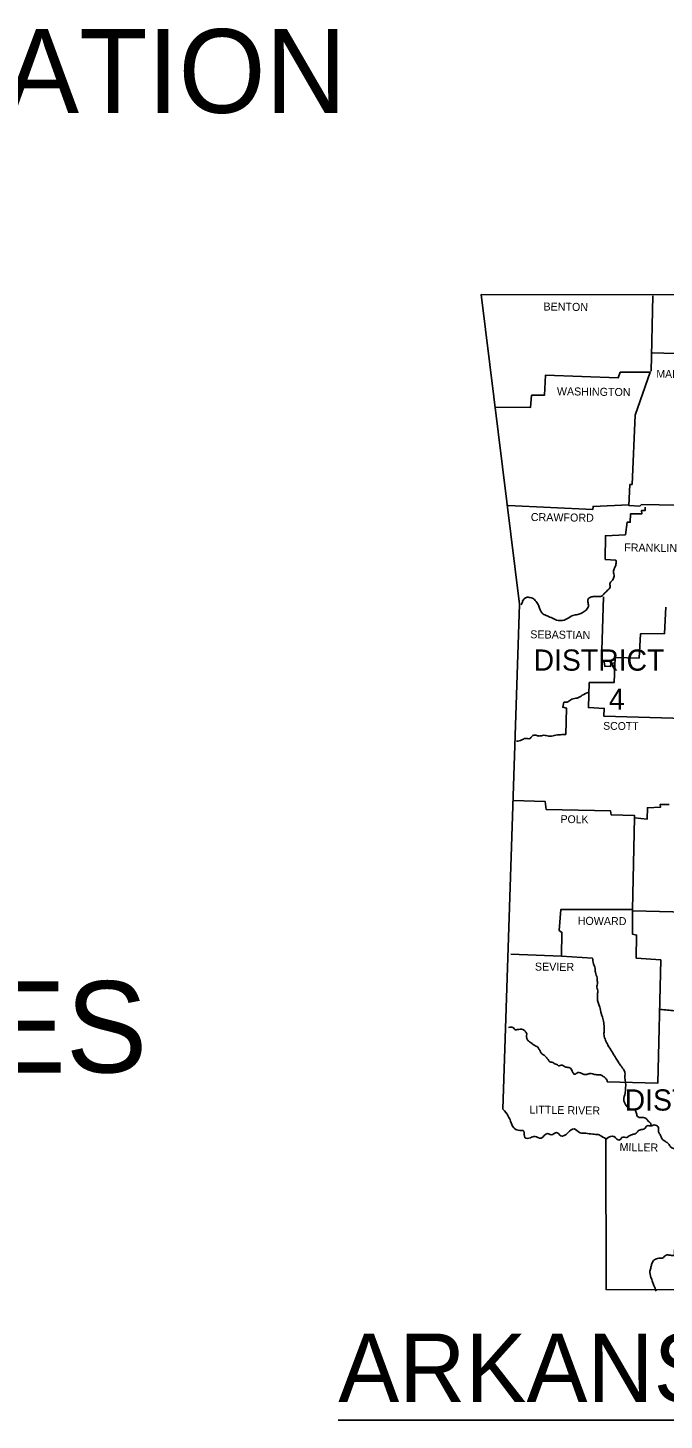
# Model space of a CAD drawing. Extents: x -2512 to 3792, y -435 to 2624.
# Drawn here: x 2465 to 2800, y 1365 to 2097 of the extents above; entities that cross this region are included whole.
import ezdxf

# ---------------------------------------------------------------- set-up
doc = ezdxf.new("R2010")
doc.units = 0
for name, color, linetype in [('1', 7, 'Continuous'), ('2', 7, 'Continuous'), ('3', 7, 'Continuous')]:
    doc.layers.add(name, color=color, linetype=linetype)

msp = doc.modelspace()

# ---------------------------------------------------------------- linework, layer by layer
at = {"layer": '1'}
for points in [[(2703.71, 1956.42), (2861.92, 1956.32), (3000.75, 1956.61), (3164.54, 1959.16), (3240.46, 1960.92)], [(2703.71, 1956.42), (2723.96, 1793.81), (2715.15, 1528.37)], [(2794.01, 1955.83), (2793.13, 1916.21)], [(2793.82, 1925.89), (2817.89, 1925.11), (2818.47, 1921.98), (2821.8, 1921.88), (2821.7, 1919.92), (2824.05, 1919.34), (2824.25, 1908.67), (2827.28, 1907.99), (2827.48, 1903.78), (2831.78, 1903.19), (2831.98, 1899.28), (2840.49, 1898.4), (2862.4, 1898.89), (2862.6, 1955.15)], [(2711.44, 1897.22), (2729.73, 1897.13), (2730.22, 1903.58), (2736.97, 1903.58), (2737.56, 1914.05), (2775.72, 1912.68), (2776.89, 1915.62), (2792.64, 1915.72), (2784.72, 1893.02), (2783.15, 1856.72), (2781.98, 1856.62), (2781.39, 1845.66), (2787.17, 1845.17), (2788.05, 1846.05), (2834.72, 1845.17), (2835.21, 1839.99)], [(2717.89, 1845.56), (2762.41, 1843.51), (2762.61, 1845.08), (2781.2, 1845.96)], [(2790, 1844.78), (2790, 1843.02), (2788.14, 1843.02), (2788.24, 1841.26), (2782.27, 1841.16), (2782.18, 1836.76), (2780.51, 1836.76), (2779.63, 1830.2), (2769.06, 1829.71), (2768.97, 1817.29), (2774.64, 1816.9)], [(2767.99, 1797.53), (2767.01, 1763.87), (2768.48, 1763.48), (2768.77, 1761.13), (2771.71, 1760.93), (2772, 1762.6), (2774.35, 1762.99)], [(2800.86, 1792.24), (2800.18, 1778.25), (2787.46, 1778.15), (2786.77, 1765.43), (2774.15, 1765.73), (2773.76, 1752.62), (2760.55, 1752.52), (2760.16, 1739.41), (2768.48, 1738.92), (2768.18, 1734.91), (2810.65, 1733.73)], [(2748.32, 1725.22), (2748.62, 1739.02), (2746.66, 1739.6), (2747.25, 1742.25)], [(2720.54, 1690.59), (2737.46, 1690), (2737.85, 1685.89), (2771.71, 1685.2), (2772.1, 1683.05), (2784.43, 1682.66), (2784.33, 1680.8)], [(2802.53, 1688.53), (2797.93, 1688.53), (2798.03, 1686.97), (2791.18, 1686.77), (2791.08, 1680.8), (2784.43, 1681.39), (2783.35, 1633.25), (2745.68, 1633.35), (2744.8, 1622.19), (2746.17, 1621.22), (2746.07, 1608.69), (2719.36, 1609.87)], [(2783.35, 1633.25), (2783.35, 1620.24), (2785.5, 1619.85), (2785.31, 1607.71), (2798.22, 1606.74), (2796.66, 1542.06), (2770.04, 1542.75)], [(2783.55, 1632.57), (2839.51, 1631.1)], [(2746.07, 1608.69), (2762.31, 1607.71)], [(2769.26, 1512.61), (2769.46, 1433.46), (3128.04, 1432.87)]]:
    msp.add_lwpolyline(points, dxfattribs=at)
for points in [[(2774.64, 1816.9), (2774.64, 1814.84), (2773.86, 1812.69), (2773.37, 1810.83), (2773.66, 1808.39), (2772.78, 1806.43), (2771.51, 1804.86), (2771.51, 1802.91), (2770.04, 1800.85), (2768.48, 1799.29), (2767.11, 1798.01), (2764.66, 1797.82), (2762.61, 1797.72), (2760.55, 1797.04), (2759.77, 1795.57), (2760.16, 1793.32), (2759.38, 1791.17), (2757.32, 1789.5), (2755.07, 1788.43), (2752.73, 1788.03), (2749.5, 1786.47), (2746.56, 1785.2), (2743.43, 1785.39), (2740.5, 1786.66), (2737.85, 1787.84), (2735.8, 1789.01), (2734.14, 1792.63), (2733.06, 1794.59), (2731.2, 1796.55), (2728.95, 1797.33), (2727.09, 1797.13), (2724.84, 1793.32)], [(2747.25, 1742.25), (2749.4, 1742.44), (2751.45, 1743.81), (2754.19, 1744.4), (2756.93, 1745.87), (2760.36, 1747.43)], [(2748.32, 1725.22), (2745.49, 1725.12), (2742.26, 1724.73), (2739.32, 1724.34), (2736.68, 1724.83), (2734.23, 1724.44), (2732.57, 1724.83), (2730.52, 1724.34), (2729.34, 1723.17), (2726.9, 1723.17), (2725.13, 1722.38), (2722.3, 1721.7)], [(2762.31, 1607.71), (2762.8, 1604.78), (2763.68, 1602.24), (2763.78, 1600.28), (2764.66, 1597.34), (2764.66, 1596.27), (2764.96, 1594.11), (2764.56, 1592.94), (2765.05, 1590.59), (2764.96, 1588.83), (2764.96, 1587.36), (2765.05, 1584.92), (2765.84, 1582.76), (2766.62, 1579.54), (2767.11, 1577.87), (2767.89, 1575.33), (2768.38, 1572.2), (2768.48, 1569.85), (2768.28, 1567.7), (2768.87, 1565.25), (2769.95, 1562.81), (2771.32, 1560.46), (2772.98, 1557.82), (2774.15, 1555.76), (2775.62, 1553.51), (2776.79, 1551.65), (2778.56, 1549.3), (2779.34, 1547.35), (2779.34, 1544.61), (2779.73, 1542.06), (2779.63, 1539.23), (2779.44, 1536.68), (2778.75, 1533.16), (2779.24, 1531.5), (2781.1, 1529.05), (2782.27, 1528.37), (2784.33, 1527.97), (2785.31, 1526.6), (2785.89, 1524.55), (2787.95, 1523.86), (2790.2, 1523.67), (2791.27, 1522.49), (2792.74, 1520.93), (2793.23, 1520.15)], [(2798.03, 1580.71), (2801.74, 1580.42), (2805.17, 1580.03), (2807.81, 1579.73), (2810.55, 1578.75), (2813, 1577.87), (2814.56, 1577.19), (2817.2, 1577.38), (2819.45, 1576.89), (2822, 1576.01), (2823.86, 1574.35), (2825.03, 1573.08), (2827.28, 1572.59), (2829.14, 1572.88), (2831.39, 1572.69), (2833.93, 1571.9), (2835.99, 1572), (2837.65, 1572.39), (2839.61, 1572.88), (2842.05, 1573.08), (2843.91, 1572.69), (2846.36, 1572.59), (2849.2, 1572.88), (2852.72, 1571.9)], [(2718.19, 1571.22), (2720.34, 1571.32), (2721.81, 1570.05), (2722.69, 1570.14), (2724.25, 1570.34), (2725.72, 1570.24), (2726.8, 1569.36), (2727.68, 1567.8), (2727.58, 1566.33), (2727.68, 1565.74), (2728.36, 1564.47), (2729.54, 1563.49), (2730.81, 1562.51), (2731.98, 1561.73), (2733.94, 1560.46), (2734.14, 1560.07), (2734.92, 1558.5), (2735.9, 1557.23), (2737.07, 1556.45), (2738.34, 1555.08), (2738.93, 1554.49), (2739.91, 1553.12), (2740.98, 1553.02), (2742.45, 1552.14), (2743.53, 1551.85), (2744.7, 1551.06), (2745.88, 1551.46), (2747.34, 1550.87), (2749.3, 1550.28), (2750.38, 1550.09), (2751.65, 1548.23), (2752.92, 1546.66), (2754.49, 1547.54), (2757.42, 1546.66), (2759.28, 1546.56), (2760.94, 1547.05), (2762.22, 1546.96), (2764.56, 1546.37), (2766.03, 1546.37), (2767.6, 1545.78), (2769.06, 1544.61), (2770.04, 1543.34), (2770.04, 1542.75)], [(2715.15, 1528.37), (2717.99, 1524.65), (2719.17, 1522.01), (2720.83, 1518.58), (2723.28, 1517.21), (2726.11, 1516.72), (2726.7, 1513.4), (2729.63, 1513.3), (2731.98, 1513.98), (2735.21, 1513.1), (2738.64, 1515.45), (2740.59, 1514.86), (2743.43, 1516.04), (2745.58, 1514.28), (2749.3, 1515.84), (2752.63, 1517.99), (2755.76, 1515.94), (2758.79, 1515.65), (2762.41, 1515.16), (2765.25, 1514.96), (2767.79, 1513.69), (2769.65, 1512.42), (2769.26, 1512.61)], [(2769.26, 1512.61), (2772.68, 1514.08), (2774.15, 1513.59), (2775.42, 1512.32), (2776.89, 1512.32), (2777.67, 1513.49), (2779.14, 1513.59), (2780.32, 1513.49), (2781.59, 1514.28), (2782.66, 1514.77), (2784.13, 1515.25), (2785.21, 1515.65), (2786.19, 1516.72), (2787.95, 1517.6), (2790, 1518.29), (2790.59, 1519.27), (2791.57, 1519.66), (2793.52, 1519.56), (2794.8, 1520.15), (2795.87, 1519.66), (2796.85, 1518.97), (2797.05, 1516.43), (2797.83, 1515.06), (2799, 1512.61), (2800.67, 1511.34), (2802.23, 1510.07), (2802.82, 1509.29), (2804.48, 1507.82), (2805.95, 1507.33), (2806.64, 1506.25), (2807.71, 1503.71), (2809.28, 1501.46)], [(2809.28, 1501.46), (2808.69, 1498.62), (2808.59, 1496.37), (2809.08, 1493.73), (2808.59, 1492.46), (2809.38, 1490.6), (2810.84, 1489.13), (2811.92, 1487.57), (2812.6, 1485.32), (2811.72, 1482.77), (2812.7, 1480.13), (2813.58, 1479.15), (2814.07, 1477.59), (2813.39, 1474.55), (2812.51, 1472.3), (2810.55, 1470.05), (2809.96, 1468.98), (2810.26, 1467.51), (2810.74, 1465.16), (2810.26, 1464.48), (2808.98, 1462.81), (2808.59, 1460.95), (2807.71, 1459.39), (2806.73, 1456.55), (2805.46, 1454.2), (2805.27, 1451.56), (2803.31, 1451.56), (2801.06, 1451.56), (2799, 1450.09), (2797.15, 1450), (2794.89, 1449.11), (2793.52, 1447.26), (2793.04, 1445.2), (2792.45, 1443.24), (2793.04, 1439.92), (2793.92, 1437.57), (2794.6, 1435.71), (2795.78, 1432.68)]]:
    msp.add_spline(points, degree=3, dxfattribs=at)
at = {"layer": '2'}
msp.add_line((2628.58, 1364.87), (3283.1, 1364.87), dxfattribs=at)

# ---------------------------------------------------------------- texts
for s, height, p in [('ARKANSAS DEPARTMENT OF TRANSPORTATION', 44.0283, (1232.79, 2051.97)), ('ASHLEY,  DREW & JEFFERSON COUNTIES', 48, (1215.69, 1547.59)), ('ARKANSAS HIGHWAY DISTRICT 2', 36, (2628.58, 1374.37))]:
    msp.add_text(s, height=height, dxfattribs=at).set_placement(p)
for s, height, rotation, p in [('BENTON', 4.207, 359.25271, (2736.48, 1948.1)), ('MADISON', 4.109, 359.09062, (2795.87, 1912.78)), ('WASHINGTON', 4.206, 359.23201, (2743.53, 1903.58)), ('CRAWFORD', 4.206, 359.27706, (2729.83, 1837.44)), ('FRANKLIN', 4.207, 359.18154, (2778.95, 1821.5)), ('SEBASTIAN', 4.206, 359.28159, (2729.54, 1775.8)), ('SCOTT', 4.109, 359.40628, (2767.89, 1727.76)), ('POLK', 4.108, 359.21518, (2745.49, 1678.75)), ('HOWARD', 4.207, 359.51446, (2754.49, 1625.23)), ('SEVIER', 4.207, 359.42706, (2731.98, 1601.16)), ('LITTLE RIVER', 4.2073, 359.16968, (2729.05, 1526.02)), ('MILLER', 4.206, 359.13195, (2776.5, 1506.35))]:
    msp.add_text(s, height=height, rotation=rotation, dxfattribs=at).set_placement(p)
at = {"layer": '3'}
for s, height, p in [('DISTRICT', 11.154, (2731.3, 1758.78)), ('4', 11.15, (2770.92, 1738.23)), ('DISTRICT', 11.154, (2779.19, 1527.57))]:
    msp.add_text(s, height=height, dxfattribs=at).set_placement(p)

doc.saveas('drawing.dxf')
